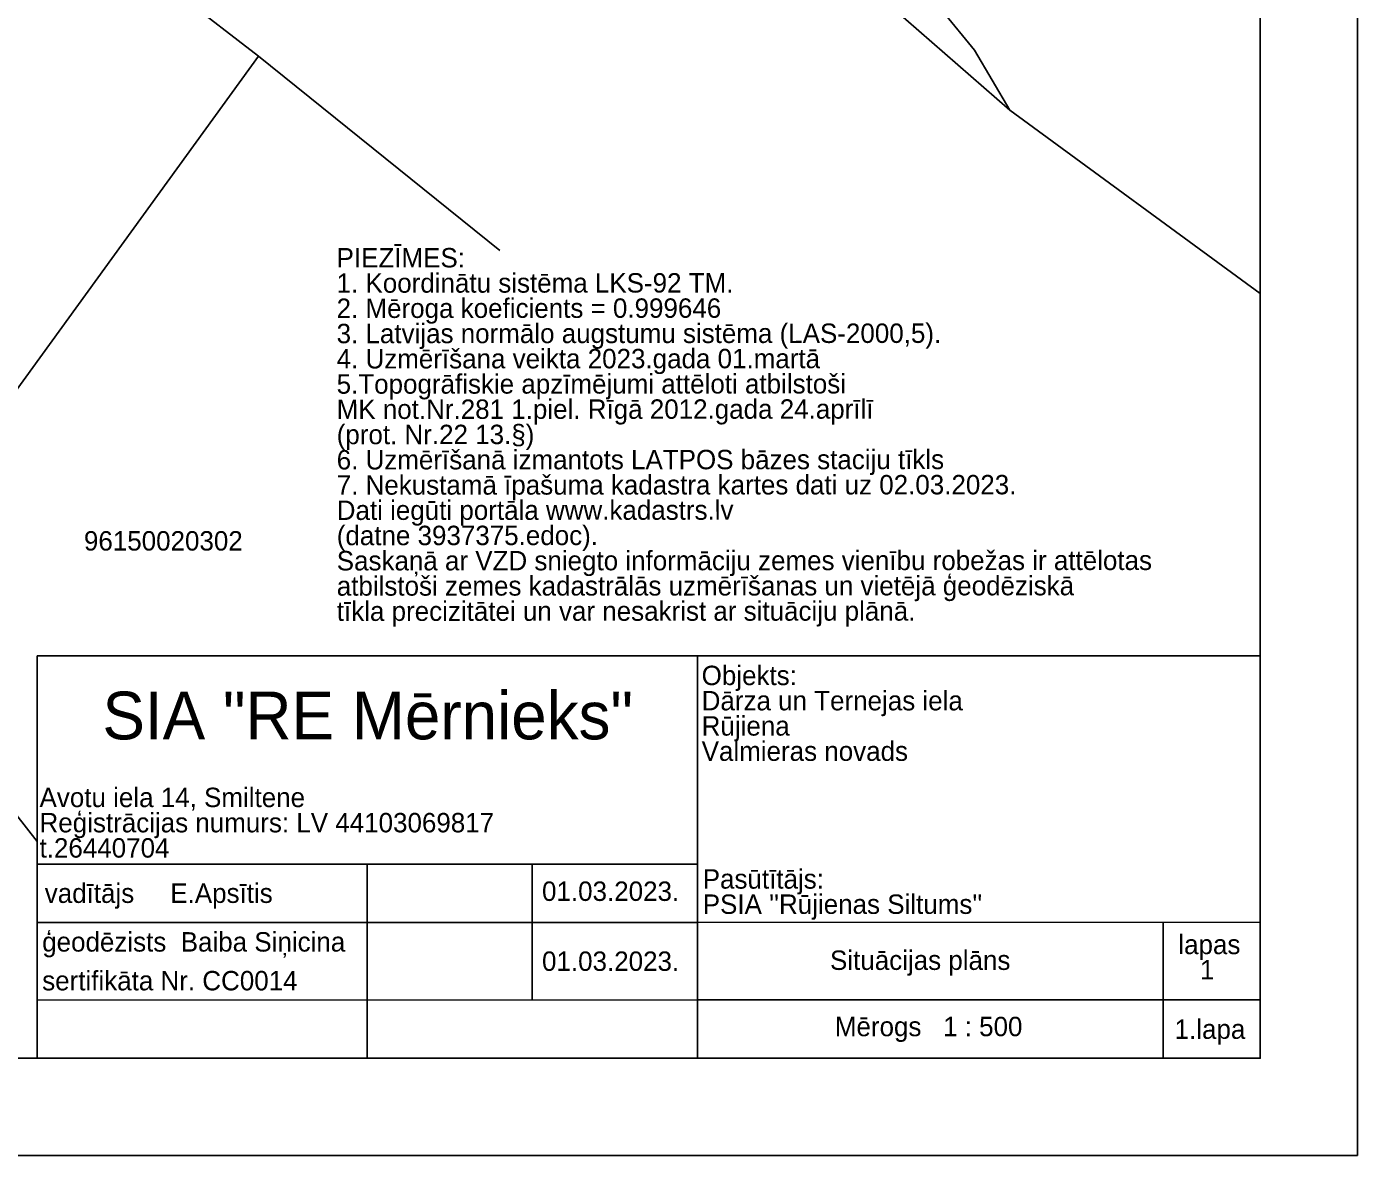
# Model space of a CAD drawing. Extents: x 578395 to 578590, y 418519 to 418816.
# Drawn here: x 578521.8 to 578590.4, y 418519.1 to 418577.2 of the extents above; entities that cross this region are included whole.
import ezdxf

# ---------------------------------------------------------------- set-up
doc = ezdxf.new("R2010")
doc.units = 0
for name, color, linetype in [('RAMI_PLAN_####_TKST_#', 7, 'Continuous'), ('ROBZ_PROJ_####_####_#', 7, 'Continuous'), ('ROBZ_UZMR_####_####_#', 7, 'Continuous'), ('ROBZ_UZMR_####_TKST_#', 7, 'Continuous')]:
    doc.layers.add(name, color=color, linetype=linetype)

msp = doc.modelspace()

# ---------------------------------------------------------------- linework, layer by layer
at = {"layer": 'RAMI_PLAN_####_TKST_#'}
for p, q in [((578590.351, 418519.111), (578590.351, 418667.611)), ((578522.351, 418534.111), (578556.352, 418534.112)), ((578539.352, 418524.111), (578539.352, 418534.111)), ((578547.851, 418527.111), (578547.851, 418534.111)), ((578522.352, 418531.111), (578556.352, 418531.111)), ((578580.351, 418531.112), (578580.351, 418524.112)), ((578585.351, 418524.111), (578585.351, 418531.112)), ((578522.351, 418527.11), (578556.351, 418527.112)), ((578556.351, 418527.112), (578580.352, 418527.112)), ((578580.352, 418527.112), (578585.351, 418527.112)), ((578556.351, 418524.111), (578585.351, 418524.111)), ((578590.351, 418519.111), (578395.351, 418519.111))]:
    msp.add_line(p, q, dxfattribs=at)
msp.add_lwpolyline([(578410.351, 418811.111), (578410.351, 418524.111), (578585.351, 418524.111), (578585.351, 418811.111)], close=True, dxfattribs=at)
for points in [[(578556.351, 418524.111), (578556.351, 418544.829), (578522.351, 418544.828), (578522.351, 418524.111), (578556.351, 418524.111)], [(578556.351, 418544.829), (578585.35, 418544.83), (578585.351, 418531.112), (578556.352, 418531.11), (578556.351, 418544.829)]]:
    msp.add_lwpolyline(points, dxfattribs=at)
at = {"layer": 'ROBZ_PROJ_####_####_#'}
for p, q in [((578456.044, 418635.726), (578533.748, 418575.711)), ((578572.447, 418572.931), (578564.357, 418579.991)), ((578570.63, 418576.021), (578568.995, 418578.021)), ((578572.447, 418572.931), (578570.63, 418576.021)), ((578585.351, 418563.493), (578572.447, 418572.931))]:
    msp.add_line(p, q, dxfattribs=at)
at = {"layer": 'ROBZ_UZMR_####_####_#'}
for p, q in [((578513.707, 418548.097), (578533.748, 418575.711)), ((578533.748, 418575.711), (578546.17, 418565.705)), ((578522.351, 418535.28), (578513.014, 418547.143))]:
    msp.add_line(p, q, dxfattribs=at)

# ---------------------------------------------------------------- texts
at = {"layer": 'RAMI_PLAN_####_TKST_#'}
for s, height, rotation, p in [('PIEZĪMES:', 1, 0.03112, (578537.769, 418564.831)), ('1. Koordinātu sistēma LKS-92 TM.', 1, 0.03112, (578537.77, 418563.531)), ('2. Mēroga koeficients = 0.999646', 1, 0.03112, (578537.77, 418562.231)), ('3. Latvijas normālo augstumu sistēma (LAS-2000,5).', 1, 0.03112, (578537.771, 418560.931)), ('4. Uzmērīšana veikta 2023.gada 01.martā', 1, 0.03112, (578537.772, 418559.631)), ('5.Topogrāfiskie apzīmējumi attēloti atbilstoši', 1, 0.03112, (578537.772, 418558.331)), ('MK not.Nr.281 1.piel. Rīgā 2012.gada 24.aprīlī', 1, 0.03112, (578537.773, 418557.031)), ('(prot. Nr.22 13.§)', 1, 0.03112, (578537.774, 418555.731)), ('6. Uzmērīšanā izmantots LATPOS bāzes staciju tīkls', 1, 0.03112, (578537.775, 418554.431)), ('7. Nekustamā īpašuma kadastra kartes dati uz 02.03.2023.', 1, 0.03112, (578537.775, 418553.131)), ('Dati iegūti portāla www.kadastrs.lv ', 1, 0.03112, (578537.776, 418551.831)), ('(datne 3937375.edoc).', 1, 0.03112, (578537.777, 418550.531)), ('Saskaņā ar VZD sniegto informāciju zemes vienību robežas ir attēlotas ', 1, 0.03112, (578537.777, 418549.231)), ('atbilstoši zemes kadastrālās uzmērīšanas un vietējā ģeodēziskā ', 1, 0.03112, (578537.778, 418547.931)), ('tīkla precizitātei un var nesakrist ar situāciju plānā.', 1, 0.03112, (578537.779, 418546.631)), ('Objekts: ', 1, 359.99963, (578556.574, 418543.326)), ('SIA "RE Mērnieks"', 2.45592, 0.00101, (578525.706, 418540.534)), ('Dārza un Ternejas iela', 1, 359.99963, (578556.574, 418542.026)), ('Rūjiena', 1, 359.99963, (578556.574, 418540.726)), ('Valmieras novads', 1, 359.99963, (578556.574, 418539.426)), ('Avotu iela 14, Smiltene', 0.99998, 0.00101, (578522.467, 418537.044)), ('Reģistrācijas numurs: LV 44103069817', 0.99998, 0.00101, (578522.467, 418535.744)), ('t.26440704', 1, 0.00101, (578522.467, 418534.444)), ('Pasūtītājs:', 0.99998, 359.99963, (578556.629, 418532.846)), ('vadītājs     E.Apsītis', 0.99998, 0.00101, (578522.736, 418532.111)), ('01.03.2023.', 1, 0.00101, (578548.351, 418532.214)), ("PSIA ''Rūjienas Siltums''", 0.99998, 359.99963, (578556.629, 418531.546)), ('ģeodēzists  Baiba Siņicina', 0.99998, 0.00101, (578522.604, 418529.605)), ('lapas', 1, 0.00101, (578581.128, 418529.473)), ('01.03.2023.', 1, 0.00101, (578548.351, 418528.611)), ('Situācijas plāns', 1, 0.00069, (578563.186, 418528.661)), ('   1', 1, 0.00101, (578581.128, 418528.173)), ('sertifikāta Nr. CC0014', 0.99998, 0.00101, (578522.604, 418527.607)), ('Mērogs   1 : 500', 0.99998, 0.00101, (578563.435, 418525.247)), ('1.lapa', 1, 0.00101, (578580.937, 418525.111))]:
    msp.add_text(s, height=height, rotation=rotation, dxfattribs=at).set_placement(p)
at = {"layer": 'ROBZ_UZMR_####_TKST_#'}
msp.add_text('96150020302', height=1, dxfattribs=at).set_placement((578524.754, 418550.255))

doc.saveas('drawing.dxf')
